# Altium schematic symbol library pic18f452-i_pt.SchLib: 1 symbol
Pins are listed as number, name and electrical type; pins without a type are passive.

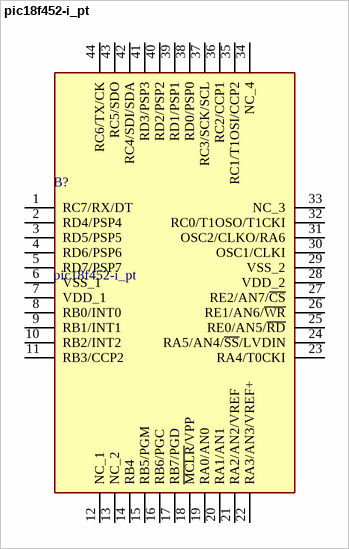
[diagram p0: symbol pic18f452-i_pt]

## pic18f452-i_pt
designator B?
PIC18F452-I/PT, 8 bit PIC Microcontroller 40MHz 32 kB Flash, 1536 B RAM, I2C 44-Pin TQFP; Manufacturer_Name: Microchip; Geometry.Height: 1.2mm
footprint QFP80P1200X1200X120-44N
pins: 1 RC7/RX/DT, 2 RD4/PSP4, 3 RD5/PSP5, 4 RD6/PSP6, 5 RD7/PSP7, 6 VSS_1, 7 VDD_1, 8 RB0/INT0, 9 RB1/INT1, 10 RB2/INT2, 11 RB3/CCP2, 12 NC_1, 13 NC_2, 14 RB4, 15 RB5/PGM, 16 RB6/PGC, 17 RB7/PGD, 18 ~{MCLR}/VPP, 19 RA0/AN0, 20 RA1/AN1, 21 RA2/AN2/VREF, 22 RA3/AN3/VREF+, 23 RA4/T0CKI, 24 RA5/AN4/~{SS}/LVDIN, 25 RE0/AN5/~{RD}, 26 RE1/AN6/~{WR}, 27 RE2/AN7/~{CS}, 28 VDD_2, 29 VSS_2, 30 OSC1/CLKI, 31 OSC2/CLKO/RA6, 32 RC0/T1OSO/T1CKI, 33 NC_3, 34 NC_4, 35 RC1/T1OSI/CCP2, 36 RC2/CCP1, 37 RC3/SCK/SCL, 38 RD0/PSP0, 39 RD1/PSP1, 40 RD2/PSP2, 41 RD3/PSP3, 42 RC4/SDI/SDA, 43 RC5/SDO, 44 RC6/TX/CK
